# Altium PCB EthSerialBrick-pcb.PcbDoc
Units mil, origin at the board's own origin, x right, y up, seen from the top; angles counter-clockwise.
Board outline 3550 x 3775 mil, 4 copper layers (Top Layer, Internal Plane 1, Internal Plane 2, Bottom Layer); 63 components, 33 nets, 228 pads, 11 vias.
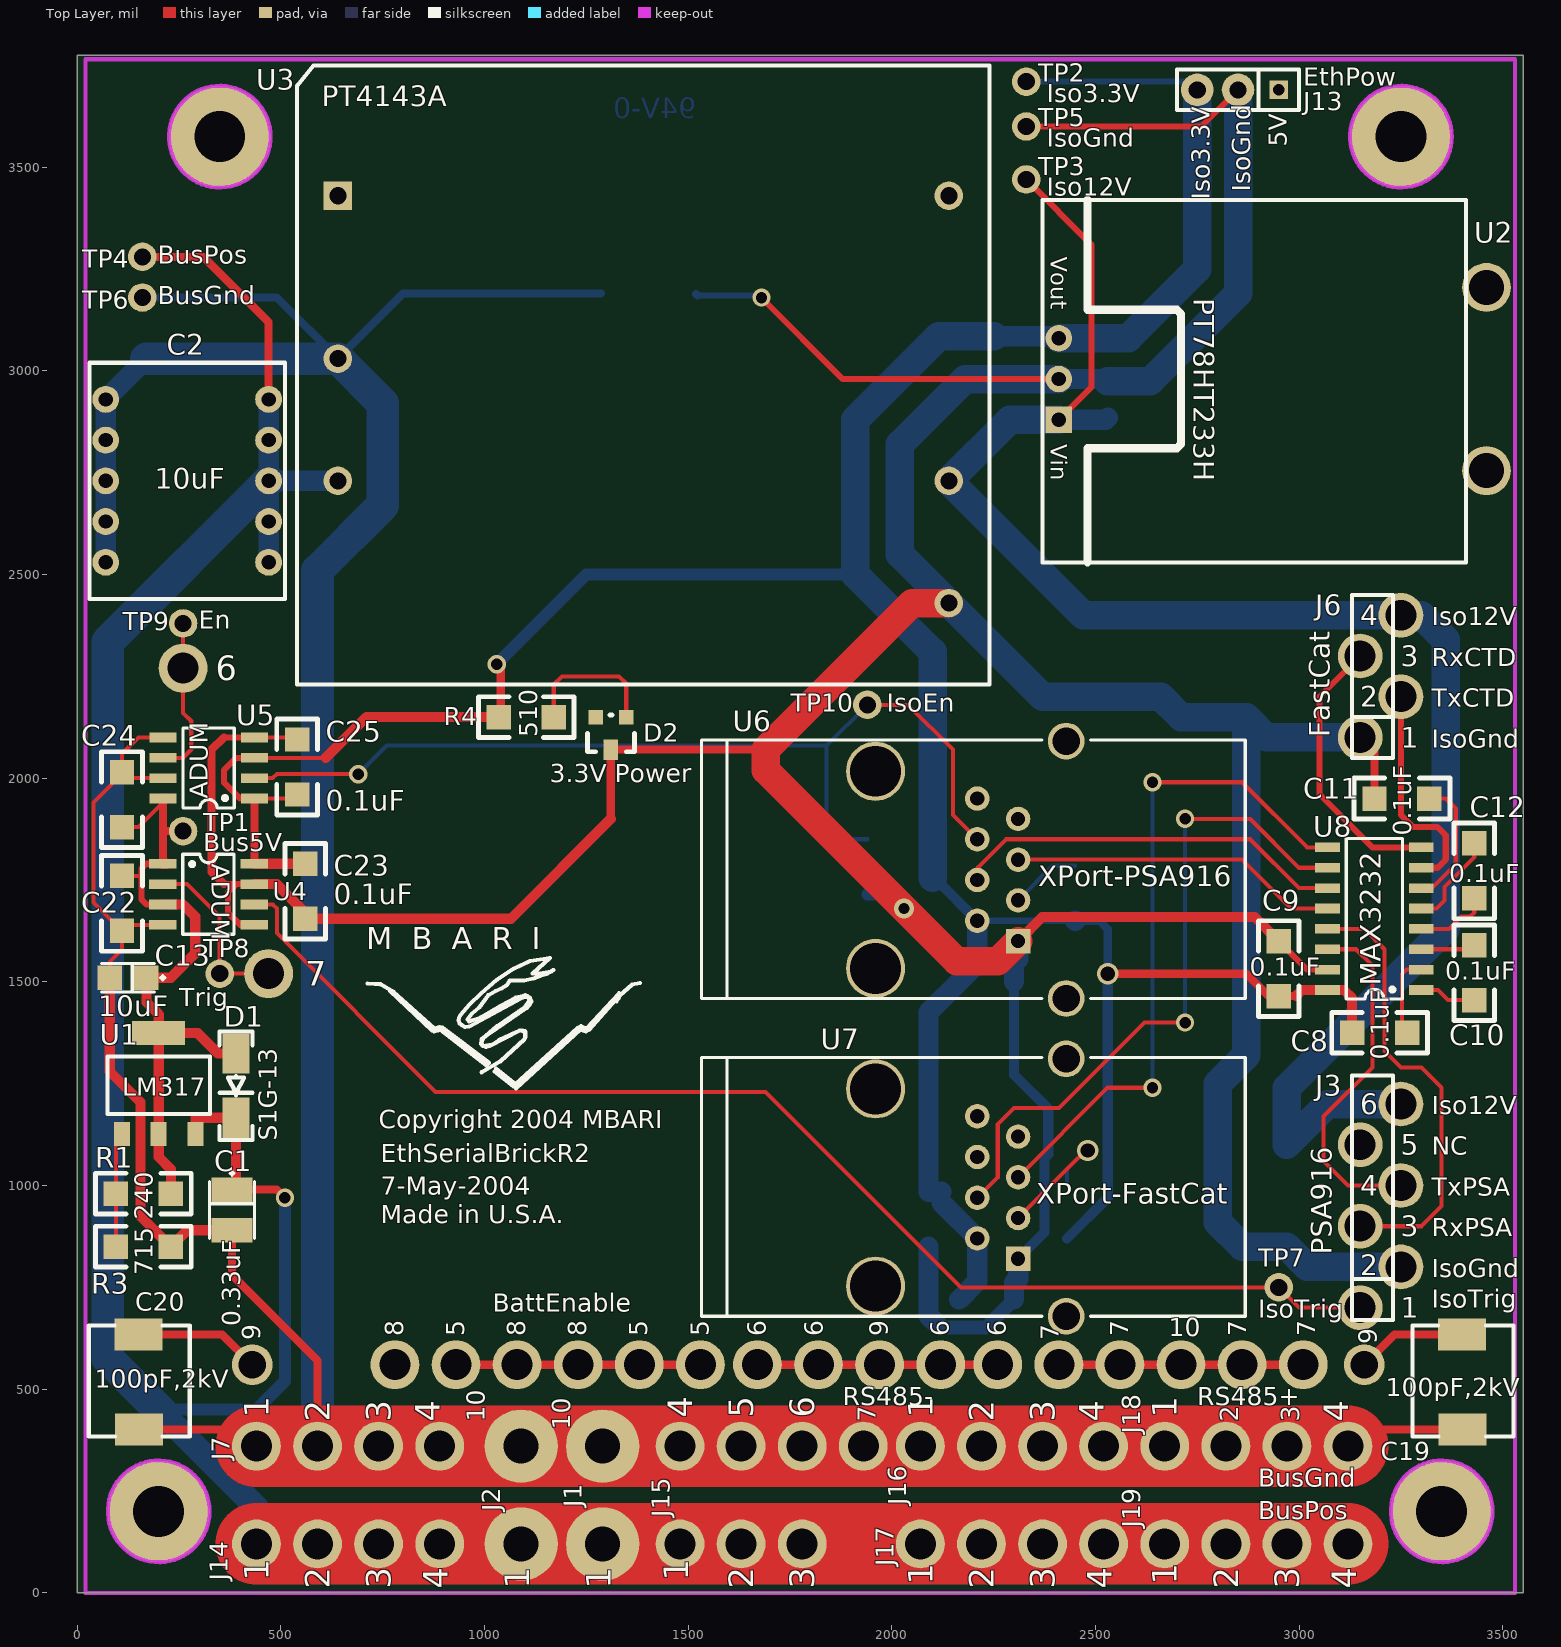
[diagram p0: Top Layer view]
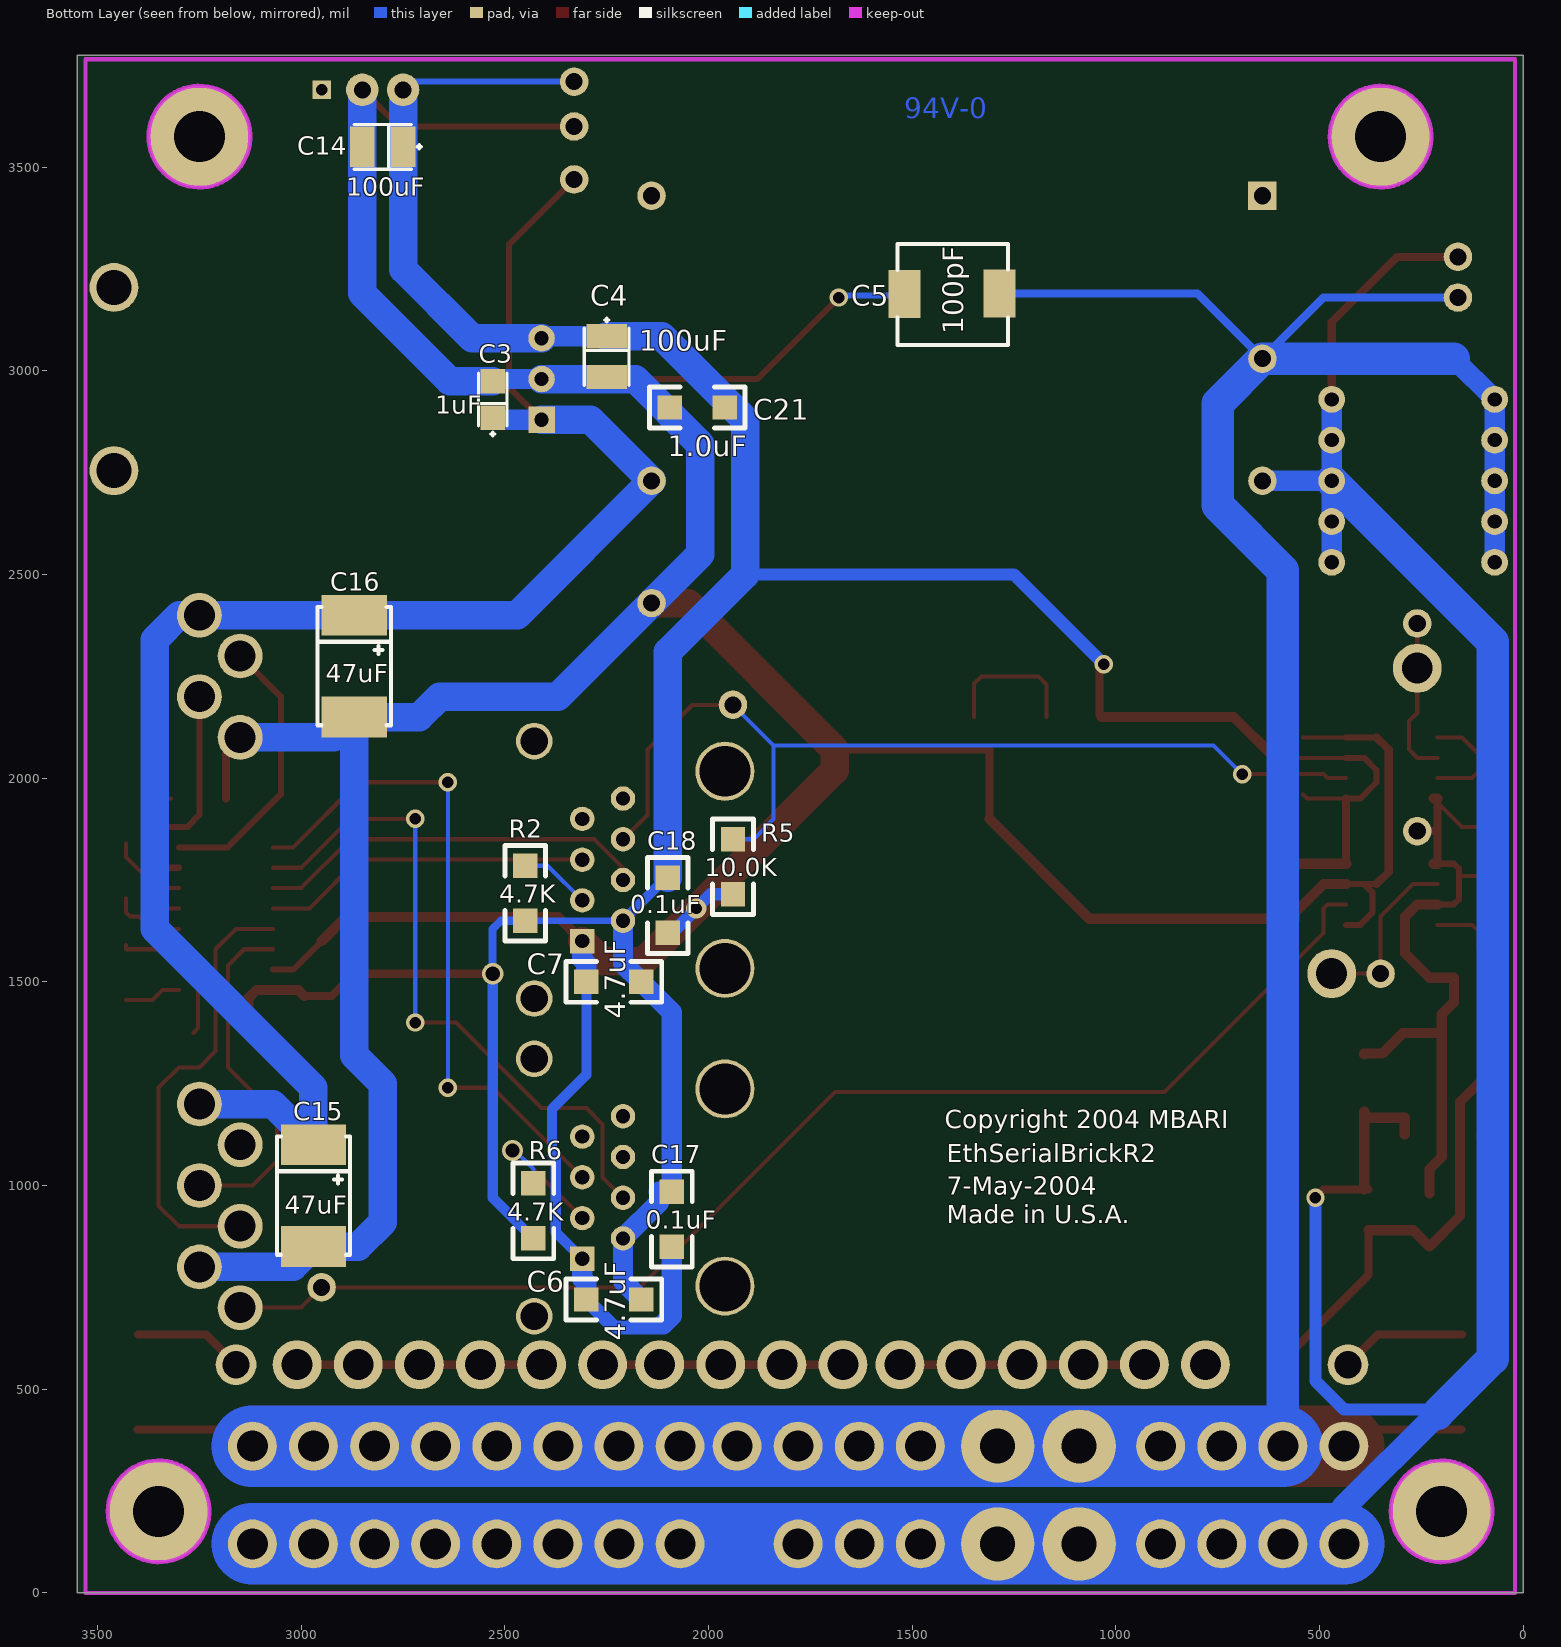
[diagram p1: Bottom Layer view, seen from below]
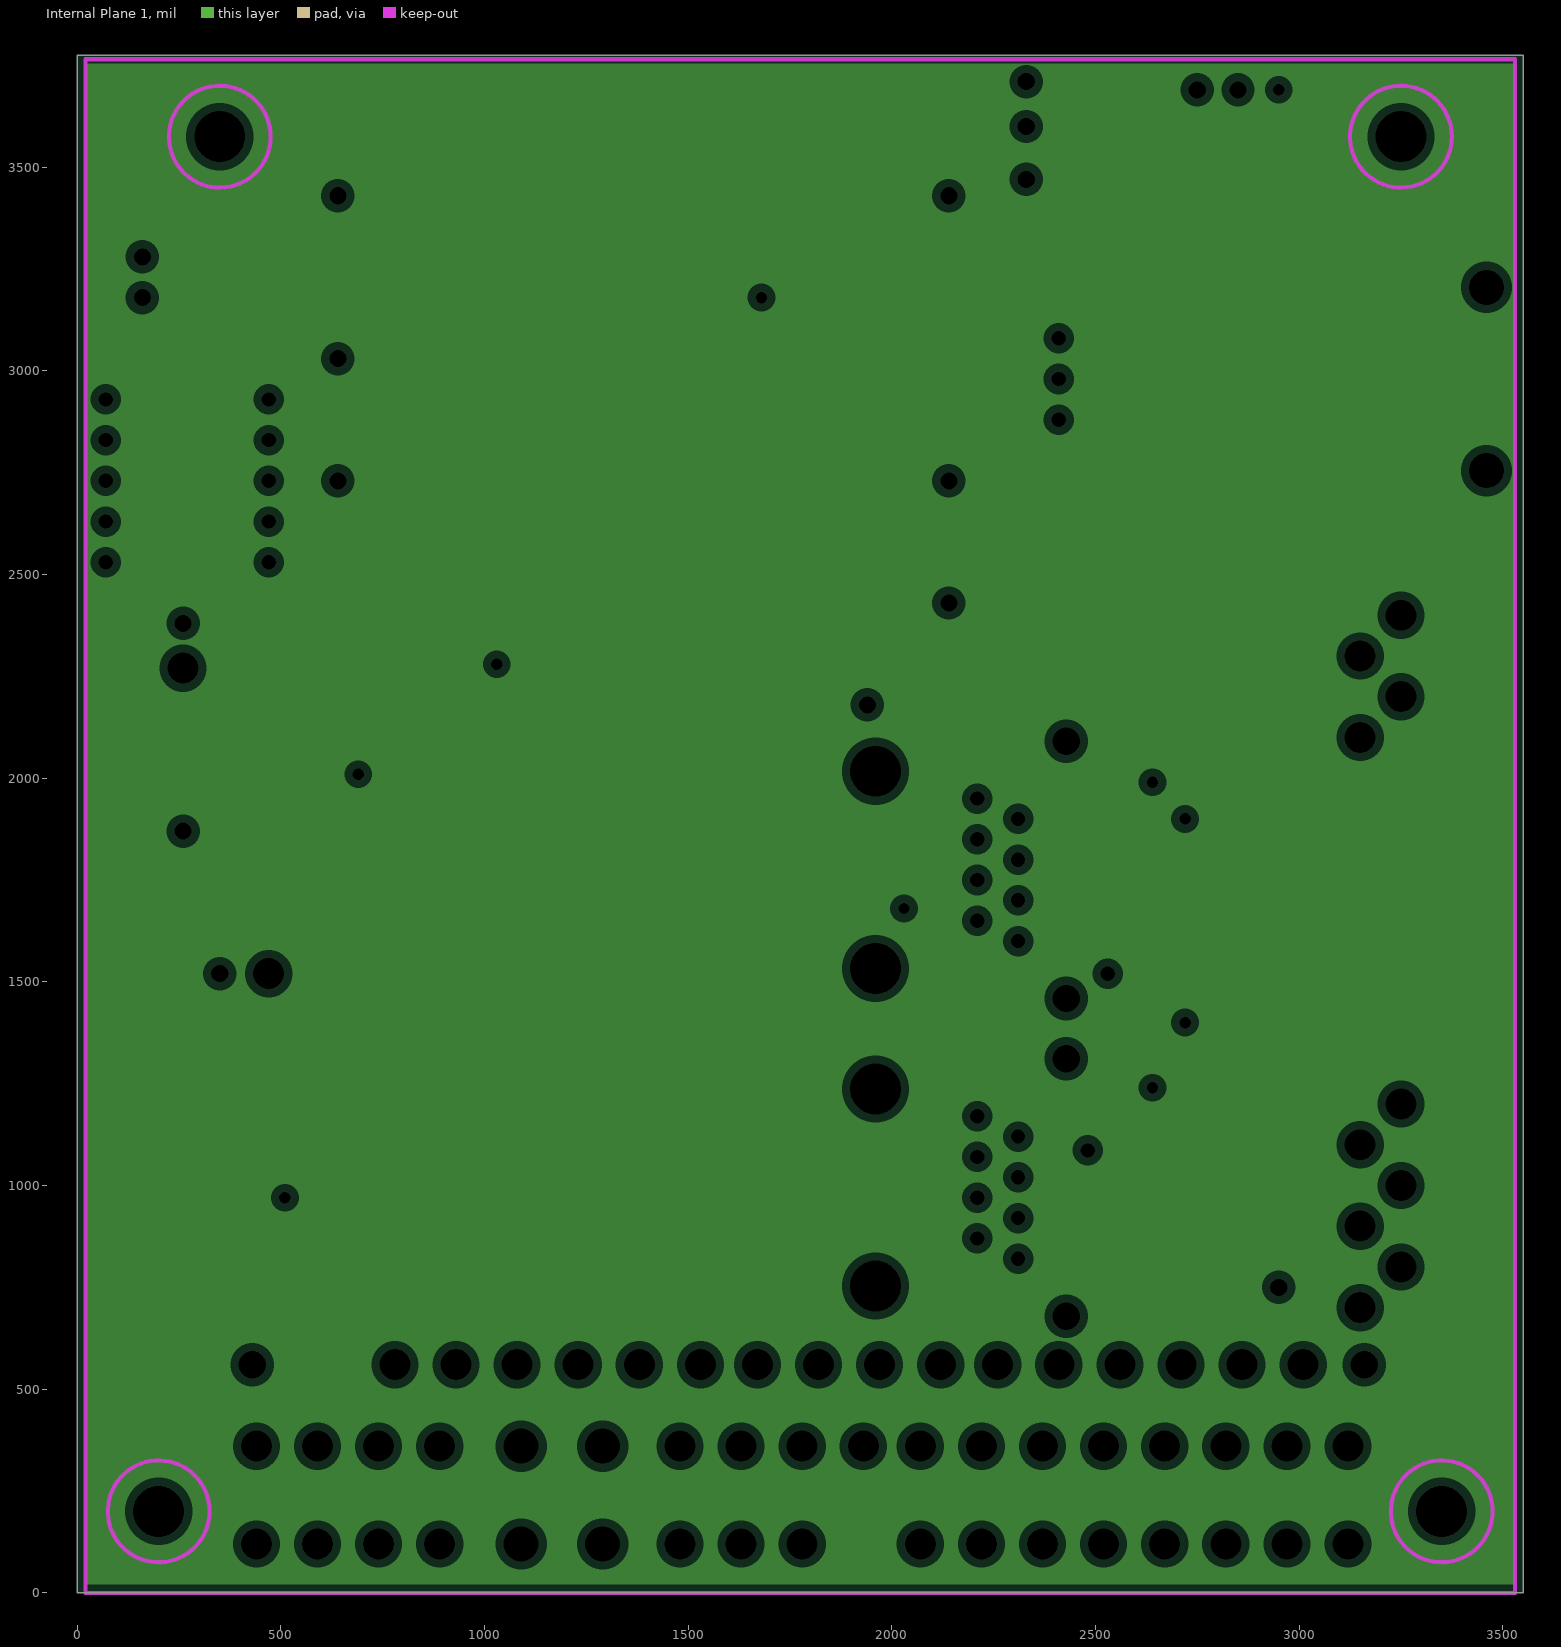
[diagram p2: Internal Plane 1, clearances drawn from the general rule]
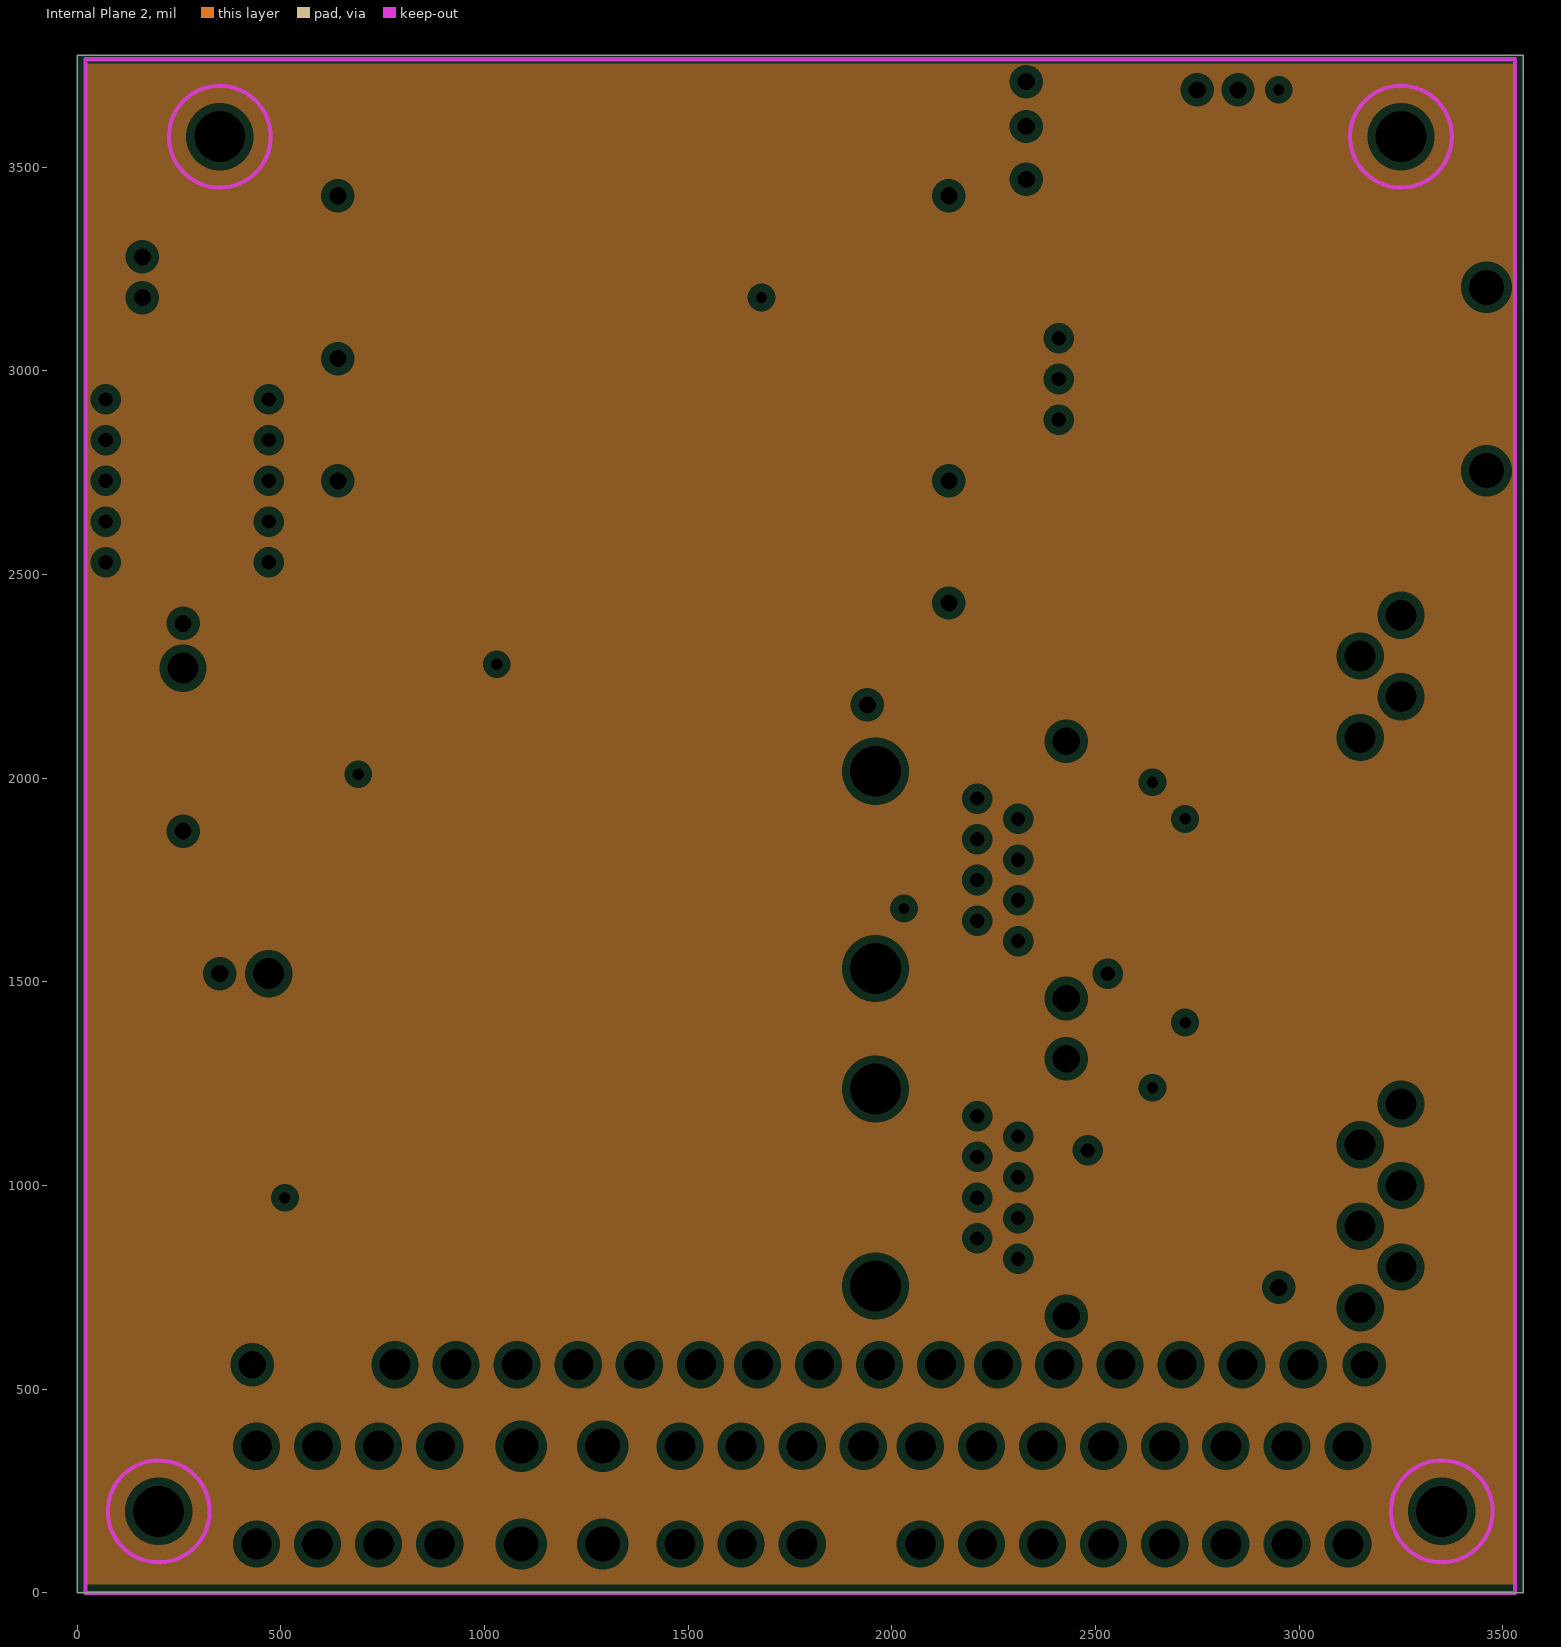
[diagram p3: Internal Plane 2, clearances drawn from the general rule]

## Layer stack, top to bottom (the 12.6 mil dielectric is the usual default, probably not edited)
Top Layer: signal copper 1.4
Dielectric: dielectric 12.6, FR-4, Dk 4.8
Internal Plane 1: plane copper 1.4
Dielectric: dielectric 12.6, FR-4, Dk 4.8
Internal Plane 2: plane copper 1.4
Dielectric: dielectric 12.6, FR-4, Dk 4.8
Bottom Layer: signal copper 1.4

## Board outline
0,0 0,3775 3550,3775 3550,0

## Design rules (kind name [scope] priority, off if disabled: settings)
Clearance Clearance_poly [InPolygon] p1: gap=16 // poly
Clearance [All] p2: gap=10
ComponentClearance [All] p1 off: gap=10 collisioncheckmode=0
FanoutControl Fanout_Small [(CompPinCount < 5)] p1: bgadir=Out bgaviamode=Centered fanoutstyle=Auto fanoutdirection=OutThenIn viagrid=1 // Fanout_Small (Default Rule)
FanoutControl Fanout_Default [All] p2: bgadir=Out bgaviamode=Centered fanoutstyle=Auto fanoutdirection=Alternating viagrid=1 // Fanout_Default (Default Rule)
FanoutControl Fanout_BGA [IsBGA] p4: bgadir=Out bgaviamode=Centered fanoutstyle=Auto fanoutdirection=Alternating viagrid=1 // Fanout_BGA (Default Rule)
FanoutControl Fanout_LCC [IsLCC] p5: bgadir=Out bgaviamode=Centered fanoutstyle=Auto fanoutdirection=Alternating viagrid=1 // Fanout_LCC (Default Rule)
HoleSize [All] p1: absolutevalues=TRUE maxlimit=152 minlimit=1 maxpercent=80.000 minpercent=20.000
MinimumAnnularRing [All] p1: minimumring=7.5
PlaneClearance [All] p1: clearance=20
PlaneConnect [All] p1: planeconnectstyle=Relief reliefexpansion=20 reliefentries=4 reliefconductorwidth=10 reliefairgap=10
PolygonConnect [All] p1: connectstyle=Relief reliefconductorwidth=10 reliefentries=4 polygonreliefangle="90 Angle"
RoutingLayers [All] p1: top layer=Horizontal bottom layer=Vertical
RoutingVias [All] p1: holewidth=28 width=45 viastyle="Through Hole" minholewidth=28 minwidth=43 maxholewidth=86 maxwidth=101
SolderMaskExpansion [All] p1: expansion=4
TestPointUsage [All] p1: valid=0 allowmultiple=FALSE
Testpoint [All] p1: side=15 testpointundercomponent=TRUE minsize=40 maxsize=100 preferedsize=60 minholesize=0 maxholesize=40 preferedholesize=32 testpointgrid=1 style=1023 order=1234567890
Width Width_power [InNetClass('Power')] p1: maxlimit=250 minlimit=10 preferedwidth=10 toplayer_prefwidth=25 bottomlayer_prefwidth=30 minimp=50.000000 maximp=50.000000 favimp=50.000000 // power width rule
Width [All] p2: maxlimit=250 minlimit=8 preferedwidth=12 toplayer_prefwidth=10 bottomlayer_prefwidth=10 minimp=50.000000 maximp=50.000000 favimp=50.000000
9 further rules are at their usual default settings.

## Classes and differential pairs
net class Power: BUS5V BUSGND BUSPOS ISO3.3V ISO12V ISOGND

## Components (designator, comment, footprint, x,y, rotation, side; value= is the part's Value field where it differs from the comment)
C1 "0.33uF" 3528POL 380,990 r270 top
C2 "10uF" CAPSTICK-CS4-5 470,2930 r270 top
C3 "1uF" 3216POL 2530,2885 r90 bottom
C4 "100uF" 3528POL 2250,3085 r270 bottom
C5 "100pF" ECK 1280,3170 r0 bottom
C6 "4.7uF" 1206 2165,720 r0 bottom
C7 "4.7uF" 1206 2165,1500 r0 bottom
C8 "0.1uF" 1206 3265,1375 r180 top
C9 "0.1uF" 1206 2950,1465 r90 top
C10 "0.1uF" 1206 3430,1455 r90 top
C11 "0.1uF" 1206 3185,1950 r0 top
C12 "0.1uF" 1206 3430,1705 r90 top
C13 "10uF" 3216POL 170,1510 r180 top
C14 "100uF" 3528POL 2750,3550 r0 bottom
C15 "47uF" 7343pol 2970,1100 r270 bottom
C16 "47uF" 7343pol 2870,2400 r270 bottom
C17 "0.1uF" 1206 2090,985 r270 bottom
C18 "0.1uF" 1206 2100,1755 r270 bottom
C19 "100pF,2kV" ECK 3420,640 r270 top
C20 "100pF,2kV" ECK 170,640 r270 top
C21 "1.0uF" 1206 1960,2910 r0 bottom
C22 "0.1uF" 1206 110,1760 r270 top
C23 "0.1uF" 1206 560,1790 r270 top
C24 "0.1uF" 1206 110,1880 r90 top
C25 "0.1uF" 1206 540,1960 r90 top
D1 "S1G-13" SMA 390,1245 r270 top
D2 "3.3V Power" SOT-23 1273,2150 r180 top
J1 "Bus Aft/MVC" MINK-10-SOLDERPADS#1 1290,120 r90 top locked
J2 "Bus Fwd/MBE" MINK-10-SOLDERPADS#2 1090,120 r90 top locked
J3 "PSA916" SIP6 3180,720 r90 top
J6 "FastCat" SIP4 3180,2100 r90 top
J7 "Batt3Neg" LPIL-7-SOLDERPADS#1 440,360 r90 top locked
J13 "EthPow" SIP3 2950,3690 r180 top
J14 "B3Pos" LPIL-4-SOLDERPADS 440,120 r90 top
J15 "Charge Tether" MINM-10-SOLDERPADS 1480,120 r90 top
J16 "Batt2Neg" LPIL-7-SOLDERPADS#2 2070,360 r90 top locked
J17 "B2Pos" LPIL-4-SOLDERPADS 2070,120 r90 top
J18 "Batt1Neg" LPIL-7-SOLDERPADS#3 2670,360 r90 top
J19 "B1Pos" LPIL-4-SOLDERPADS 2670,120 r90 top
R1 "240" 1206 230,980 r180 top
R2 "4.7K" 1206 2450,1785 r270 bottom
R3 "715" 1206 230,850 r180 top
R4 "510" 1206 1035,2150 r0 top
R5 "10.0K" 1206 1940,1715 r90 bottom
R6 "4.7K" 1206 2430,1005 r270 bottom
TP1 "Bus5V" TP-PAD-35 260,1870 r0 top
TP2 "Iso3.3V" TP-PAD-35 2330,3710 r0 top
TP3 "Iso12V" TP-PAD-35 2330,3470 r0 top
TP4 "BusPos" TP-PAD-35 160,3280 r0 top
TP5 "IsoGnd" TP-PAD-35 2330,3600 r0 top
TP6 "BusGnd" TP-PAD-35 160,3180 r0 top
TP7 "IsoTrig" TP-PAD-35 2950,750 r90 top
TP8 "Trig" TP-PAD-35 350,1520 r0 top
TP9 "En" TP-PAD-35 260,2380 r90 top
TP10 "IsoEn" TP-PAD-35 1940,2180 r270 top
U1 "LM317EMP" SOT-223 200,1250 r0 top
U2 "PT78HT233H" PT78ST-HORIZ 2410,2980 r270 top
U3 "PT4143A" TI-EGD 640,3430 r0 top locked
U4 "=ManufPartNo" SO-G8/D5 210,1790 r270 top
U5 "=ManufPartNo" SO-G8/D5 435,1950 r90 top
U6 "XPort-PSA916" XPORT 2310,1600 r0 top
U7 "XPort-FastCat" XPORT 2310,820 r0 top
U8 "MAX3232" SOIC-16-0.15W 3300,1480 r90 top

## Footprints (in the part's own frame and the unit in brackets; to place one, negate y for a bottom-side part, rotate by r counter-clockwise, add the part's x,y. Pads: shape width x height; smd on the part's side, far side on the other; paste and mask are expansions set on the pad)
1206 [mil]
  rect 60x60 smd: 1(0,0) 2(135,0)
  silkscreen extent -50,-50 185,50
3216POL [mil] "Polarized Cap EIA-3216-18, similiar to1206 footprint"
  rect 60x60 smd: 1(0,0) 2(90,0)
  silkscreen extent -45,-35 110,35
3528POL [mil] "Polarized chip capacitor EIA 3528-21"
  rect 60x100 smd: 1(0,0) 2(100,0)
  silkscreen extent -45,-55 120,55
7343pol [mil] "Polarized chip cap EIA 7343-31"
  rect 100x160 smd: 1(0,0) 2(250,0)
  silkscreen extent -20,-90 270,90
CAPSTICK-CS4-5 [mil]
  round 66 hole 35: 1(0,0) 1(100,0) 1(200,0) 1(300,0) 1(400,0) 2(0,-400) 2(100,-400) 2(200,-400) 2(300,-400) 2(400,-400)
  silkscreen extent -90,-440 490,40
ECK [mm]
  rect 2x3 smd: 1(0.15,-0.5) 2(6.075,-0.475)
  silkscreen extent -0.4,-3.6 6.5,2.7
LPIL-4-SOLDERPADS [mil]
  round 120 hole 76: 1(0,0) 2(0,-150) 3(0,-300) 4(0,-450)
LPIL-7-SOLDERPADS#1 [mil]
  round 120 hole 76: 1(0,0) 2(0,-150) 3(0,-300) 4(0,-450) 5(200,-490) 6(200,-1230) 7(200,-1970)
LPIL-7-SOLDERPADS#2 [mil]
  round 120 hole 76: 1(0,0) 2(0,-150) 3(0,-300) 4(0,-450) 5(200,690) 6(200,-50) 7(200,-790)
LPIL-7-SOLDERPADS#3 [mil]
  round 120 hole 76: 1(0,0) 2(0,-150) 3(0,-300) 4(0,-450) 5(200,1140) 6(200,410) 7(200,-340)
MINK-10-SOLDERPADS#1 [mil]
  round 180 hole 86: 1(0,0) 10(240,0)
  round 120 hole 76: 6(440,-530) 7(440,-1270) 8(440,210)
  round 100 hole 67: 9(440,-1870)
MINK-10-SOLDERPADS#2 [mil]
  round 180 hole 86: 1(0,0) 10(240,0)
  round 120 hole 76: 6(2150,830) 7(1400,620) 8(440,310)
  round 100 hole 67: 9(440,660)
MINM-10-SOLDERPADS [mil] "MIN-M 10/16AWG holes"
  round 120 hole 76: 1(0,0) 2(0,-150) 3(0,-300) 4(240,0) 5(240,-150) 6(240,-300) 7(240,-450) 8(440,250) 9(440,-490) 10(440,-1230)
PT78ST-HORIZ [mil]
  round 120 hole 86: 0(-225,1050) 0(225,1050)
  rect 65x65 hole 35: 1(100,0)
  round 65 hole 35: 2(0,0) 3(-100,0)
  silkscreen extent -440,-40 450,1000
SIP3 [mil]
  rect 45x45 hole 28: 1(0,0)
  round 80 hole 42: 2(100,0) 3(200,0)
  silkscreen extent -50,-50 250,50
SIP4 [mil]
  round 110 hole 76: 1(0,30) 2(100,-70) 3(200,30) 4(300,-70)
  silkscreen extent -50,-50 350,50
SIP6 [mil]
  round 110 hole 76: 1(-20,30) 2(80,-70) 3(180,30) 4(280,-70) 5(380,30) 6(480,-70)
  silkscreen extent -50,-50 550,50
SMA [mm] "SMA Diode"
  rect 2.5x1.7 smd: 1(-2,0) 2(2,0)
  silkscreen extent -3.38,-1.02 3.38,1.02
SO-G8/D5 [mm]
  rect 0.6x1.7 smd: 1(0,0) 2(1.27,0) 3(2.54,0) 4(3.81,0) 5(3.81,5.7) 6(2.54,5.7) 7(1.27,5.7) 8(0,5.7)
  silkscreen extent -0.59,1.25 4.41,4.45
SOIC-16-0.15W [mm] "SOIC-16 0.15\"Wide 1.27mm Pitch"
  rect 0.6x1.55 smd: 1(0,0) 2(1.27,0) 3(2.54,0) 4(3.81,0) 5(5.08,0) 6(6.35,0) 7(7.62,0) 8(8.89,0) 9(8.89,5.85) 10(7.62,5.85) 11(6.35,5.85) 12(5.08,5.85) 13(3.81,5.85) 14(2.54,5.85) 15(1.27,5.85) 16(0,5.85)
  silkscreen extent -0.55,1.18 9.44,4.67
SOT-23 [mil]
  rect 36x36 smd: 1(0,0) 2(-75,0)
  rect 36x50 smd: 3(-37,80)
  silkscreen extent -95,-5 20,85
SOT-223 [mm] "4 lead SMD NS:MP04A"
  rect 1x1.5 smd: 1(-2.3,-3.15) 2(0,-3.15) 3(2.3,-3.15)
  rect 3.3x1.5 smd: 4(0,3.15)
  silkscreen extent -3.2,-1.9 3.2,1.7
TI-EGD [mil] "TI Powertrends EGD package for isol DC->DC converters"
  rect 70x70 hole 42: 1(0,0)
  round 70 hole 42: 2(0,-400) 3(0,-700) 4(1500,-1000) 5(1500,-700) 6(1500,0)
  silkscreen extent -100,-1200 1600,320
TP-PAD-35 [mil] "TestPoint 35mil"
  round 70 hole 42: 0(0,0)
XPORT [mil]
  round 145 hole 125: 0(-350,-67) 0(-350,417)
  rect 60x60 hole 35: 1(0,0)
  round 60 hole 35: 2(-100,50) 3(0,100) 4(-100,150) 5(0,200) 6(-100,250) 7(0,300) 8(-100,350)
  round 90 hole 67: 9(118,-141) 10(118,491)
  silkscreen extent -777,-141 558,494

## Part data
C1 C3 C4 C13 C14 C15 C16: library part "CAPACITOR POL", "Capacitor"
C2 C6 C7 C8 C9 C10 C11 C12 C17 C18 C19 C20 C21 C22 C23 C24 C25: library part CAPACITOR, "Capacitor"
C5: library part Cap, "Capacitor"
D1: library part DIODE_S, "Diode"
D2: library part LED, "LED"
J1 J2 J15: library part CON10, "Connector"
J3: library part CON6, "Connector"
J6 J14 J17 J19: library part CON4, "Connector"
J7 J16 J18: library part CON7, "Connector"
J13: library part CON3, "Connector"
R1 R2 R3 R4 R5 R6: library part RESISTOR, "Resistor"
TP1 TP2 TP3 TP4 TP5 TP6 TP7 TP8 TP9 TP10: library part "TP PIN", "Pad Pin for testpoints"
U1: library part LM317, "Regulator"
U2: library part PT78STXXX, "Power Trends Switching Reg"
U3: library part NPH10S, "DC->DC Isol Converter 10W"
U4 U5: library part ADUM1100AR, "Digital Isolator"
U6 U7: library part XPORT, "Serial to Ethernet Converter"
U8: library part MAX232, "MAX232 Communications Chip"

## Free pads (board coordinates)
  round 250 hole 125: 0(200,200) 0(350,3575) 0(3250,3575) 0(3350,200)

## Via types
v1: diameter 45, hole 28, Top Layer to Bottom Layer, 8 vias
v2: diameter 52, hole 35, Top Layer to Bottom Layer, 2 vias
v3: diameter 50, hole 28, Top Layer to Bottom Layer, 1 vias

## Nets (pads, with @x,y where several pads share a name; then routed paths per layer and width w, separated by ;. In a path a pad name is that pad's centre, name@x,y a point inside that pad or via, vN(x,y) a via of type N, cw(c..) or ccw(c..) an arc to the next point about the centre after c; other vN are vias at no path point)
BATTENABLE: J1.8 J7.5 J15.8 J16.5 J18.5 | length 600
  Top Layer w20: J7.5 J18.5
BUS5V: C13.1 C22.1 C24.1 D1.1 R1.1 TP1.0 U1.2 U1.4 U4.1 U4.3 U5.8 | length 1686.2
  Top Layer w10: C22.1 157.5,1760 ; C24.1 150.59,1880 210.59,1940 U5.8
  Top Layer w15: U4.3 170,1690 157.5,1702.5 157.5,1777.5 170,1790 U4.1
  Top Layer w20: U4.1@210.59,1790.59 U5.8@210.59,1940 ; 210.59,1870 TP1.0
  Top Layer w25: U4.3 260,1690 290,1660 290,1570 230,1510 C13.1 170,1450 200,1420 U1.4 ; U4.1 U4.1@220,1790 ; U5.8 U5.8@220,1950 ; R1.1 230,1040 200,1070 U1.2 U1.4 ; D1.1@390,1322 D1.1 346.26,1323.74 295.98,1374.02 U1.4
BUSGND: C1.2 C2.2 C5.1 C13.2 C19.2 C20.2 C22.2 C24.2 J1.10 J2.10 J7.1 J7.2 J7.3 J7.4 J15.4 J15.5 J15.6 J15.7 J16.1 J16.2 J16.3 J16.4 J18.1 J18.2 J18.3 J18.4 R3.1 TP6.0 U3.2 U4.4 U5.5 U5.7 | length 13317.5
  Top Layer w10: C13.2 80,1550 110,1580 C22.2 ; C24.2 125,2000 U5.7 ; U4.4 125,1640 C22.2 ; U5.5 150,2100 110,2060 110,2010 40,1940 40,1695 C22.2
  Top Layer w20: C20.2 399.17,400.83 J7.1 ; C1.2 380,780 590,570 J7.2 ; J18.4 3160.83,400.83 C19.2
  Top Layer w25: C13.2 80,1280 155,1205 155,925 R3.1 270,890 299,890 C1.2
  Top Layer w200: J7.1 J18.4
  Bottom Layer w20: TP6.0 490,3180 U3.2 799.69,3189.69 C5.1
  Bottom Layer w50: C2.2@70,2530 70,2630 70,2730 70,2830 70,2930 170,3030
  Bottom Layer w80: 170,3030 U3.2 750,2920 750,2670 590,2510 J7.2
  Bottom Layer w200: J7.2 J18.4
BUSPOS: C1.1 C2.1 D1.2 J1.1 J2.1 J14.1 J14.2 J14.3 J14.4 J15.1 J15.2 J15.3 J17.1 J17.2 J17.3 J17.4 J19.1 J19.2 J19.3 J19.4 TP4.0 U1.3 U3.3 | length 10680.1
  Top Layer w20: TP4.0 310,3280 470,3120 C2.1@470,2930 ; C1.1 490,990 v1(510,970)
  Top Layer w25: U1.3 290.55,1166.26 D1.2 ; C1.1@390,990 D1.2 ; D1.2@390,1182 D1.2
  Top Layer w200: J14.1 J19.4
  Bottom Layer w30: 200,450 440,450 510,520 v1(510,970)
  Bottom Layer w50: C2.1@470,2530 470,2630 470,2830 C2.1@470,2930 ; C2.1@470,2730 U3.3
  Bottom Layer w60: 210,440 440,210 J14.1
  Bottom Layer w80: 210,440 75,575 75,2335 C2.1@470,2730
  Bottom Layer w200: J14.1 J19.4
EN: J2.6 TP9.0 U5.6 | length 396
  Top Layer w10: U5.6 260,2050 280,2070 280,2140 260,2160 TP9.0
ISO3.3V: C4.1 C6.1 C7.1 C8.2 C9.1 C14.1 C17.1 C18.1 C21.1 C23.1 C25.1 J13.3 R2.2 R4.1 R6.2 TP2.0 U2.3 U4.8 U5.1 U5.3 U6.2 U7.2 U8.16 | length 8505.4
  Top Layer w10: U5.1 530,1950 C25.1 ; U5.3 610,2050
  Top Layer w15: U5.1 400,1950 360,1990 360,2020 390,2050 U5.3
  Top Layer w20: U4.8 435,1790.59 U5.1 ; v1(1030,2280) 1040,2270 1040,2155 R4.1 ; v2(2530,1520) 2870,1520 2925,1465 2992,1465
  Top Layer w25: U4.8 C23.1 ; 610,2050 710,2150 R4.1 ; 2992,1465 3007,1480 U8.16 3110,1480 3130,1460 C8.2
  Bottom Layer w15: U6.2 R2.2 ; TP2.0 2730,3710 J13.3
  Bottom Layer w20: R2.2 2510,1650 2530,1630 v2(2530,1520)
  Bottom Layer w25: C18.1 2105,1755 U6.2 ; 2122,958 2122,985 ; R6.2 2530,970 v2(2530,1520)
  Bottom Layer w30: v1(1030,2280) 1250,2500 1910,2500
  Bottom Layer w50: 2122,958 U7.2 2210,765 C6.1 ; 2122,985 C17.1 2090,1425 C7.1 2210,1545 U6.2 ; C4.1 2405,3085 U2.3 U2.3@2400,3080 ; R2.2 R2.2@2451,1650
  Bottom Layer w70: C18.1 2100,2310 1910,2500 1910,2880 2115,3085 C4.1 ; U2.3 2580,3080 2750,3250 J13.3
ISO12V: C3.1 C15.1 C16.1 J3.6 J6.4 TP3.0 U2.1 U3.5 | length 4248.1
  Top Layer w15: TP3.0 2490,3310 2490,2960 U2.1
  Bottom Layer w50: U2.1 2525,2880 C3.1
  Bottom Layer w70: U2.1 2290,2880 U3.5 2470,2400 3300,2400 3360,2340 3360,1630 2970,1240 C15.1 3070,1200 J3.6
ISOEN: R5.2 TP10.0 U5.2 U6.6 | length 2380.7
  Top Layer w10: U5.2 480,2000 490,2010 v1(690,2010) ; TP10.0 2040,2180 2150,2070 2150,1910 U6.6
  Bottom Layer w10: v1(690,2010) 760,2080 1840,2080 ; R5.2 1890,1850 1840,1900 1840,2080 ; TP10.0 1840,2080
ISOGND: C3.2 C4.2 C5.2 C6.2 C7.2 C9.2 C11.1 C14.2 C15.2 C16.2 C17.2 C18.2 C21.2 C23.2 C25.2 D2.3 J3.2 J6.1 J13.2 R5.1 TP5.0 U2.2 U3.4 U4.5 U4.7 U5.4 U6.1 U7.1 U8.15 | length 12798.2
  Top Layer w10: U5.4 C25.2@540,2100
  Top Layer w15: 360,1740 U4.7 ; 360,2100 U5.4 ; 390,1740 370,1720 370,1670 400,1640 U4.5 ; v1(1680,3180) 1880,2980 U2.2 ; TP5.0 2760,3600 J13.2 ; C9.2 3020,1530 U8.15
  Top Layer w20: 360,1740 330,1770 330,2070 360,2100 ; 1310,1900 D2.3 1690,2070 ; J6.1 3185,2065 C11.1
  Top Layer w25: U4.7 490,1740 560,1670 C23.2 1065,1655 1310,1900 ; U6.1 2369,1659 2891,1659 C9.2
  Top Layer w70: U3.4 2050,2430 1690,2070 1690,2020 2160,1550 2260,1550 U6.1
  Bottom Layer w15: C5.2@1522.87,3185 1675,3185 v1(1680,3180)
  Bottom Layer w20: C5.2 C5.2@1522.87,3185
  Bottom Layer w25: C7.2 2300,1272 2384,1188 2384,1076 2375,1067 2375,885 2345.5,855.5 U7.1
  Bottom Layer w30: R5.1 1995,1715 2090,1620 C18.2
  Bottom Layer w35: 2111,659 2118.5,651.5 2231.5,651.5 C6.2
  Bottom Layer w50: C17.2 2090,680 2111,659 ; C6.2 2300,761 2310,771 U7.1 ; C7.2 2300,1545 2310,1555 U6.1 ; U2.2 2525,2980 C3.2
  Bottom Layer w70: U2.2 2180,2980 2020,2820 2020,2550 2370,2200 2660,2200 2710,2150 C16.2 ; C3.2 2635,2975 2850,3190 J13.2 ; J6.1 2920,2100 C16.2 ; J3.2 3020,800 C15.2 2860,850 2800,910 2800,1250 2870,1320 C16.2
  other v3: 2030,1680
ISOTRIG: J3.1 TP7.0 U4.6 | length 3160.8
  Top Layer w10: U4.6 480,1690 490,1680 490,1620 880,1230 1690,1230 2170,750 TP7.0 3000,700 J3.1
NetC8_1: C8.1 U8.2 | length 200.5
  Top Layer w10: C8.1 3253,1387 3253,1519 3264,1530 U8.2
NetC10_1: C10.1 U8.1 | length 140.4
  Top Layer w10: U8.1 3340.51,1480 3365.51,1455 C10.1
NetC10_2: C10.2 U8.3 | length 140
  Top Layer w10: U8.3 3430,1580 C10.2
NetC11_2: C11.2 U8.6 | length 320.3
  Top Layer w10: U8.6 3325.72,1730 3384.58,1788.87 3384.58,1925.42 3360,1950 C11.2
NetC12_1: C12.1 U8.4 | length 181.6
  Top Layer w10: U8.4 3368,1630 3398,1660 3420,1660 3430,1670 C12.1
NetC12_2: C12.2 U8.5 | length 235.5
  Top Layer w10: U8.5 3337,1680 3357,1700 3357,1733 3430,1806 C12.2
NetD2_2: D2.2 R4.2 | length 355.7
  Top Layer w10: R4.2 1170,2230 1190,2250 1330,2250 1348,2232 D2.2
NetR1_2: R1.2 R3.2 U1.1 | length 282
  Top Layer w10: R3.2 R1.2 95,1101.55 109.45,1116 U1.1
NetR2_1: R2.1 U6.3 | length 175.2
  Bottom Layer w10: U6.3 2395,1785 R2.1
NetR6_1: R6.1 U7.3 | length 342.3
  Top Layer w10: U7.3 2456,1066 v2(2481,1086)
  Bottom Layer w10: R6.1 2430,1040 2456,1066 v2(2481,1086)
NetU6_4: U6.4 U8.11 | length 968.4
  Top Layer w10: U6.4 2210,1780 2280,1850 2880,1850 3000,1730 U8.11
NetU6_5: U6.5 U8.12 | length 809.4
  Top Layer w10: U6.5 2860,1800 2980,1680 U8.12
NetU7_4: U7.4 U8.10 | length 1663.7
  Top Layer w10: U7.4 2260,1020 2260,1150 2300,1190 2410,1190 2620,1400 v1(2720,1400) ; v1(2720,1900) 2880,1900 3000,1780 U8.10
  Bottom Layer w10: v1(2720,1400) v1(2720,1900)
NetU7_5: U7.5 U8.9 | length 1685.1
  Top Layer w10: U7.5 2530,1240 v1(2640,1240) ; v1(2640,1990) 2860,1990 3020,1830 U8.9
  Bottom Layer w10: U7.5 U7.5@2328,1020 ; v1(2640,1240) v1(2640,1990)
RS485+: J1.7 J7.7 J15.10 J16.7 J18.7 | length 600
  Top Layer w20: J7.7 J18.7
RS485-: J1.6 J7.6 J15.9 J16.6 J18.6 | length 590
  Top Layer w20: J7.6 J18.6
RX1: J3.3 U8.13 | length 1099
  Top Layer w10: U8.13 3160,1630 3210,1580 3210,1330 3250,1290 3300,1290 3350,1240 3350,950 3300,900 J3.3
RX2: J6.3 U8.8 | length 685.3
  Top Layer w15: J6.3 3050,2200 3050,1960 3180,1830 U8.8
SHIELD1: C19.1 J1.9 | length 271
  Top Layer w20: J1.9 3234.09,634.09 C19.1
SHIELD2: C20.1 J2.9 | length 310.4
  Top Layer w20: C20.1 355.91,634.09 J2.9
TRIG: J2.7 TP8.0 U4.2 | length 433.1
  Top Layer w10: U4.2 270,1740 349.7,1660.3 349.7,1520.3 TP8.0 J2.7
TX1: J3.4 U8.14 | length 871.4
  Top Layer w10: U8.14 3140,1580 3180,1540 3180,1290 3060,1170 3060,1060 3120,1000 J3.4
TX2: J6.2 U8.7 | length 549
  Top Layer w15: J6.2 3250,1910 3280,1880 3340,1880 3360,1860 3360,1800 3340,1780 U8.7
pads on no net: D2.1 J2.8 J3.5 J13.1 U2.0 U3.1 U3.6 U6.0 U6.7 U6.8 U6.9 U6.10 U7.0 U7.6 U7.7 U7.8 U7.9 U7.10

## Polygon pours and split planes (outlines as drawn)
no net on Internal Plane 1 (split plane): 20.01,20.01 20.01,3754.98 3529.98,3754.98 3529.98,20.01
no net on Internal Plane 2 (split plane): 20.01,20.01 20.01,3754.98 3529.98,3754.98 3529.98,20.01

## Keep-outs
Keep-Out Layer:
  circle w10: c200,200 r125
  circle w10: c350,3575 r125
  circle w10: c3250,3575 r125
  circle w10: c3350,200 r125
  lines w10: 20,0 3530,0 3530,3765 20,3765 20,0
  text ".GKO" at 15240,-540 h90

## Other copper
Top Layer:
  text ".GTL" at 15240,-540 h90
Bottom Layer:
  text "94V-0" at 1520,3620 h50
  text ".GBL" at 15240,-540 h90

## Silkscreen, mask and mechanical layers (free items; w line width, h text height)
Top Overlay:
  lines w10: 713,1496 745,1494 776,1476 877,1385 890,1389 897,1388 1011,1301 ; 768,1478 871,1381 ; 876,1378 891,1382 1006,1294 ; 993,1278 1039,1305 1098,1359 1101,1366 1101,1376 1099,1379 1093,1380 1086,1380 ; 1024,1280 1071,1243 ; 1028,1287 1076,1249 1228,1387 1237,1391 1251,1386 1330,1472 1333,1467 1362,1493 1382,1497 ; 1100,1365 1100,1373 1098,1377 1093,1379 1086,1380 ; 1234,1383 1249,1378 ; 1256,1382 1321,1455 ; 1324,1452 1330,1461 ; 1086,1380 1079,1377 1036,1357 1019,1346 996,1342 992,1347 993,1359 1031,1391 1099,1438 1110,1454 1106,1465 1100,1467 1076,1461 1040,1441 992,1413 962,1403 958,1407 969,1422 987,1437 1009,1467 1027,1477 1042,1484 1055,1492 1062,1503 1097,1503 1120,1508 1136,1514 1152,1519 1169,1529 1164,1525 1135,1520 1118,1520 1161,1559 1112,1551 1073,1533 1030,1505 991,1471 963,1444 941,1419 937,1411 936,1405 939,1398 944,1394 952,1389 962,1390 1090,1460 1100,1463 1107,1463 1111,1461 1113,1457 1115,1452 1112,1445 1104,1436 1009,1371 998,1363 994,1355 993,1349 997,1342 1004,1340 1012,1342 1086,1380 ; 1077,1238 1236,1383 1077,1238
  text "5V" at 2970,3550 h45 r90
  text "IsoGnd" at 2880,3440 h45 r90
  text "Iso3.3V" at 2780,3420 h45 r90
  text "4" at 3150,2375 h50
  text "Iso12V" at 3325,2375 h45
  text "3" at 3250,2275 h50
  text "RxCTD" at 3325,2275 h45
  text "2" at 3150,2175 h50
  text "TxCTD" at 3325,2175 h45
  text "1" at 3250,2075 h50
  text "IsoGnd" at 3325,2075 h45
  text "ADUM" at 320,1950 h45 r90
  text "ADUM" at 330,1790 h45 r270
  text "M  B  A  R  I" at 710,1580 h55
  text "LM317" at 110,1220 h45
  text "6" at 3150,1175 h50
  text "Iso12V" at 3325,1175 h45
  text "Copyright 2004 MBARI" at 740,1140 h45
  text "5" at 3250,1075 h50
  text "NC" at 3325,1075 h45
  text "EthSerialBrickR2" at 745,1056.68 h45
  text "7-May-2004" at 745,976.68 h45
  text "4" at 3150,975 h50
  text "TxPSA" at 3325,975 h45
  text "Made in U.S.A." at 745,906.68 h45
  text "3" at 3250,875 h50
  text "RxPSA" at 3325,875 h45
  text "2" at 3150,780 h50
  text "IsoGnd" at 3325,775 h45
  text "IsoTrig" at 3325,700 h45
  text "BattEnable" at 1020,690 h45
  text "1" at 3250,675 h50
  text "5" at 1400,630 h45 r90
  text "5" at 1550,630 h45 r90
  text "6" at 2140,630 h45 r90
  text "6" at 2280,630 h45 r90
  text "7" at 2870,630 h45 r90
  text "7" at 3040,630 h45 r90
  text "RS485-" at 1880,460 h45
  text "RS485+" at 2750,460 h45
  text "BusGnd" at 2900,260 h45
  text "BusPos" at 2900,180 h45
  text ".GTO" at 15240,-540 h90
Bottom Overlay:
  text "Copyright 2004 MBARI" at 1420,1140 h45
  text "EthSerialBrickR2" at 1415,1056.68 h45
  text "7-May-2004" at 1415,976.68 h45
  text "Made in U.S.A." at 1415,906.68 h45
  text ".GBO" at 15250,-540 h90
Top Solder:
  text ".GTS" at 15250,-540 h90
Bottom Solder:
  text ".GBS" at 15250,-540 h90
Drill Guide:
  text ".GG1" at 15250,-540 h90
Mechanical 4:
  the board outline again, w10
Mechanical 16:
  lines w5: -800,1950 -600,1950 ; -800,4700 -600,4700 ; -800,7450 -600,7450 ; 2000,9600 2000,9800 ; 2035,-800 2035,-600 ; 4865,-800 4865,-600 ; 4865,9600 4865,9800 ; 7700,-800 7700,-600 ; 7700,9600 7700,9800 ; 9700,0 15600,0 ; 10530,-800 10530,-600 ; 10530,9600 10530,9800 ; 11100,-300 15600,-300 ; 11100,300 12600,300 ; 12600,-600 12600,0 12600,600 ; 13365,-800 13365,-600 ; 13365,9600 13365,9800 ; 14700,-600 14700,0 ; 15600,1950 15800,1950 ; 15600,4700 15800,4700 ; 15600,7450 15800,7450 ; 11100,-600 9700,-600 9700,600 11100,600 ; 11100,-600 15600,-600 ; 11100,-600 11100,600 ; 11100,600 12600,600 ; 12600,600 15600,600 15600,-600 ; 15600,-600 -600,-600 -600,9600 15600,9600 15600,-600 ; -800,-800 -800,9800 15800,9800 15800,-800 -800,-800
  lines w10: 10033,446 10065,444 10096,426 10197,335 10210,339 10217,338 10331,251 ; 10088,428 10191,331 ; 10196,328 10211,332 10326,244 ; 10313,228 10359,255 10418,309 10421,316 10421,326 10419,329 10413,330 10406,330 ; 10344,230 10391,193 ; 10348,237 10396,199 10548,337 10557,341 10571,336 10650,422 10653,417 10682,443 10702,447 ; 10420,315 10420,323 10418,327 10413,329 10406,330 ; 10554,333 10569,328 ; 10576,332 10641,405 ; 10644,402 10650,411 ; 10406,330 10399,327 10356,307 10339,296 10316,292 10312,297 10313,309 10351,341 10419,388 10430,404 10426,415 10420,417 10396,411 10360,391 10312,363 10282,353 10278,357 10289,372 10307,387 10329,417 10347,427 10362,434 10375,442 10382,453 10417,453 10440,458 10456,464 10472,469 10489,479 10484,475 10455,470 10438,470 10481,509 10432,501 10393,483 10350,455 10311,421 10283,394 10261,369 10257,361 10256,355 10259,348 10264,344 10272,339 10282,340 10410,410 10420,413 10427,413 10431,411 10433,407 10435,402 10432,395 10424,386 10329,321 10318,313 10314,305 10313,299 10317,292 10324,290 10332,292 10406,330 ; 10397,188 10556,333 10397,188
  text "1" at 601.34,9665 h70
  text "2" at 3427,9665 h70
  text "3" at 6252,9665 h70
  text "4" at 9093.01,9665 h70
  text "5" at 11927,9665 h70
  text "6" at 14762,9665 h70
  text "A" at -725,8822 h70
  text "A" at 15675,8822 h70
  text "B" at -725,6088.02 h70
  text "B" at 15675,6088.02 h70
  text "C" at -725,3307 h70
  text "C" at 15675,3307 h70
  text "M  B  A  R  I" at 10030,500 h55
  text "ENGINEER:" at 11150,500 h45
  text "TITLE:" at 12650,500 h45
  text "D" at -725,485 h70
  text "D" at 15675,485 h70
  text "Mark Sibenac" at 11660,470 h70
  text "Ethernet to Serial Brick" at 13000,380 h90
  text "1 831 775 2028" at 11650,330 h60
  text "PCB DESIGNER:" at 11150,205 h45
  text "Mark Sibenac" at 11680,170 h70
  text "For use with Mapping AUV" at 13020,160 h90
  text "Copyright      2004" at 9880,150 h60
  text "Monterey Bay Aquarium Research Institute" at 9750,40 h45
  text "1 831 775 2028" at 11670,30 h60
  text "DATE:" at 11150,-100 h45
  text "PART NO.:" at 12650,-100 h45
  text "REV:" at 14750,-100 h45
  text ".PRINT_DATE" at 11200,-220 h70
  text "2" at 15030,-220 h90
  text "EthSerialBrickR2" at 13010,-230 h60
  text "M.B.A.R.I." at 9780,-240 h100
  text "7700 Sandholdt Rd." at 9770,-340 h60
  text "FILE NAME:" at 11150,-400 h45
  text "DWG NO:" at 12650,-400 h45
  text "GERBER:" at 14750,-400 h45
  text "Moss Landing, CA 95039" at 9770,-450 h60
  text "1002306" at 13010,-490 h60
  text ".PCB_FILE_NAME_NO_PATH" at 11200,-520 h70
  text ".GM16" at 14860,-530 h70
  text "Fax: 1 831 775 1646" at 9770,-550 h60
  text "1" at 601.34,-735 h70
  text "2" at 3427,-735 h70
  text "3" at 6252,-735 h70
  text "4" at 9093.01,-735 h70
  text "5" at 11927,-735 h70
  text "6" at 14762,-735 h70
Drill Drawing:
  text ".LEGEND" at 3675,100 h60
  text "Drill Drawing." at 3655,10 h60
  text ".GD1" at 15245,-540 h90

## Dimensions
0,0 to 3550,0 on Mechanical 4
0,3775 to 0,0 on Mechanical 4
200,200 to 0,0 on Mechanical 4
200,200 to 0,0 on Mechanical 4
